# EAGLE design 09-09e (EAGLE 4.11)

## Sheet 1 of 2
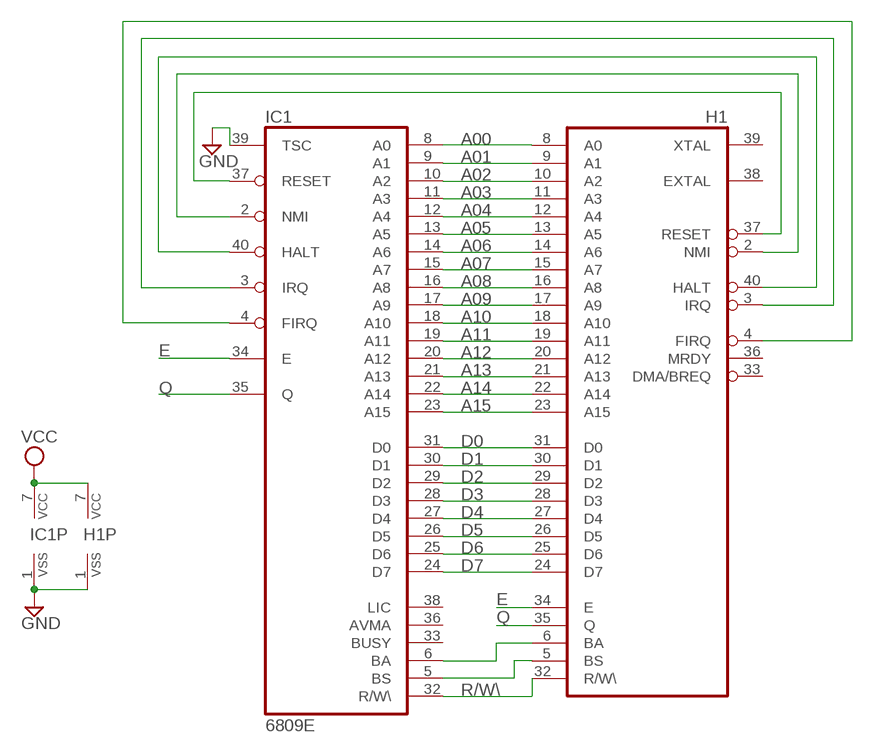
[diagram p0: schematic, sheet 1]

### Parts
H1  6809  [DIL40]
IC1  6809E  [DIL40]

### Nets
A00: H1.8(A0) IC1.8(A0)
A01: H1.9(A1) IC1.9(A1)
A02: H1.10(A2) IC1.10(A2)
A03: H1.11(A3) IC1.11(A3)
A04: H1.12(A4) IC1.12(A4)
A05: H1.13(A5) IC1.13(A5)
A06: H1.14(A6) IC1.14(A6)
A07: H1.15(A7) IC1.15(A7)
A08: H1.16(A8) IC1.16(A8)
A09: H1.17(A9) IC1.17(A9)
A10: H1.18(A10) IC1.18(A10)
A11: H1.19(A11) IC1.19(A11)
A12: H1.20(A12) IC1.20(A12)
A13: H1.21(A13) IC1.21(A13)
A14: H1.22(A14) IC1.22(A14)
A15: H1.23(A15) IC1.23(A15)
D0: H1.31(D0) IC1.31(D0)
D1: H1.30(D1) IC1.30(D1)
D2: H1.29(D2) IC1.29(D2)
D3: H1.28(D3) IC1.28(D3)
D4: H1.27(D4) IC1.27(D4)
D5: H1.26(D5) IC1.26(D5)
D6: H1.25(D6) IC1.25(D6)
D7: H1.24(D7) IC1.24(D7)
E: H1.34(E) IC1.34(E) ; also sheet 2
GND [Power]: H1.1(VSS) IC1.1(VSS) IC1.39(TSC) ; also sheet 2
N$1: H1.5(BS) IC1.5(BS)
N$4: H1.6(BA) IC1.6(BA)
N$5: H1.37(RESET) IC1.37(RESET)
N$6: H1.2(NMI) IC1.2(NMI)
N$8: H1.40(HALT) IC1.40(HALT)
N$9: H1.3(IRQ) IC1.3(IRQ)
N$10: H1.4(FIRQ) IC1.4(FIRQ)
Q: H1.35(Q) IC1.35(Q) ; also sheet 2
R/W\: H1.32(R/W\) IC1.32(R/W\)
VCC [Power]: H1.7(VCC) IC1.7(VCC) ; also sheet 2
Unconnected: H1.33(DMA/BREQ) H1.36(MRDY) H1.38(EXTAL) H1.39(XTAL) IC1.33(BUSY) IC1.36(AVMA) IC1.38(LIC)

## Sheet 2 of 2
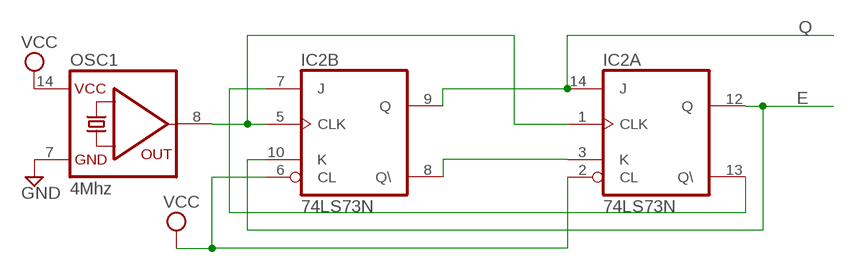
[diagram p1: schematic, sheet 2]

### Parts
IC2  74LS73N  [DIL14]
OSC1  4Mhz  QG5860  [DIL14S]

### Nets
E: IC2.10(B:K) IC2.12(A:Q) ; also sheet 1
GND [Power]: OSC1.7(GND) ; also sheet 1
N$2: IC2.1(A:CLK) IC2.5(B:CLK) OSC1.8(OUT)
N$3: IC2.3(A:K) IC2.8(B:Q\)
N$7: IC2.7(B:J) IC2.13(A:Q\)
Q: IC2.9(B:Q) IC2.14(A:J) ; also sheet 1
VCC [Power]: IC2.2(A:CL) IC2.6(B:CL) OSC1.14(VCC) ; also sheet 1

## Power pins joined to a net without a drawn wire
GND: IC2.11(P:GND)
VCC: IC2.4(P:VCC)

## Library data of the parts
H1 = micro-motorola:6809: MICROCONTROLLER/MEMORY DEVICE
IC1 = micro-motorola:6809E: MICROCONTROLLER/MEMORY DEVICE
IC2 = 74xx-us:74*73: Dual J-K FLIP FLOP, clear
OSC1 = crystal:QG5860: CRYSTAL RESONATOR

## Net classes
1 Power: width 0.508 mm, drill 0.254 mm, clearance 0.254 mm

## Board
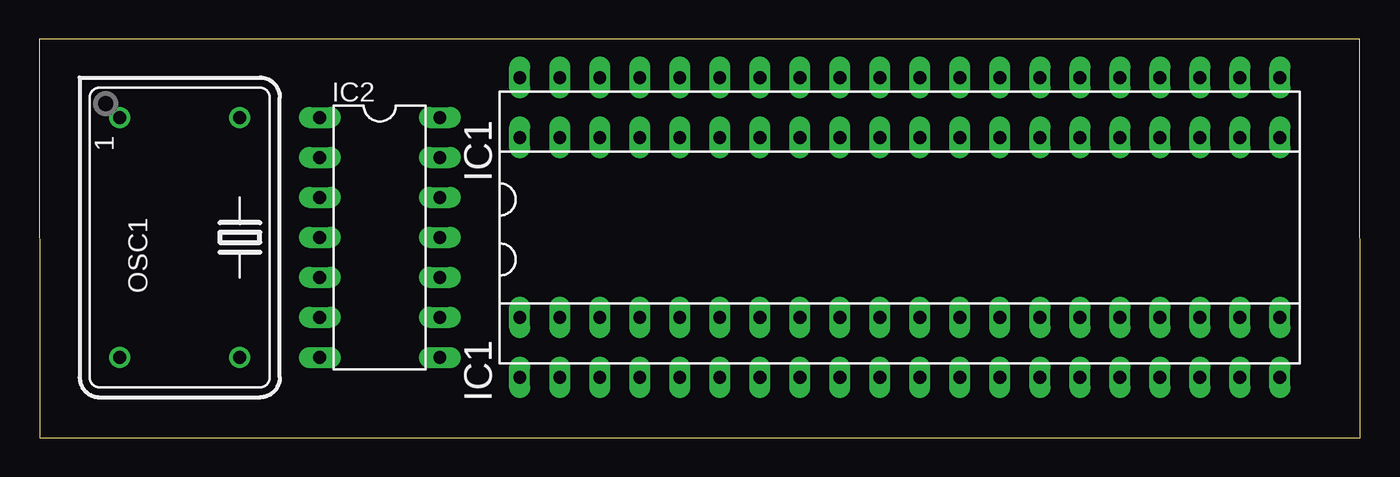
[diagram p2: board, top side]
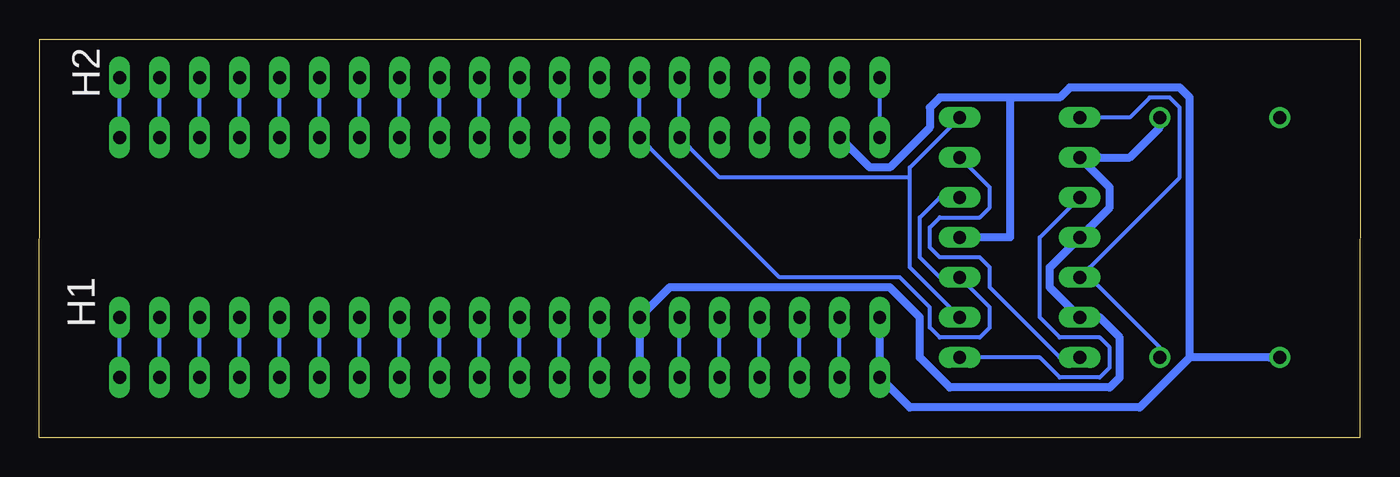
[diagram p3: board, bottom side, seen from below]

Size 83.85 x 25.3 mm. Coordinates in mm from the lower left corner, seen from the top.
Outline: 0.03,0 83.85,0 83.83,25.3 0,25.3 0.03,0
Copper layers (1*16): Top 0.035mm / dielectric 1.5mm / Bottom 0.035mm
Design rules "olimex10mil": minimum track width 10mil, minimum drill 24mil, track to track 10mil, track to pad 10mil, pad to pad 10mil, via to via 10mil, smd to smd 10mil, copper to edge 40mil, drill to drill 10mil, minimum pad ring 10mil, minimum via ring 8mil, stop-mask expansion 0mil, vias tented up to drill 0mil, thermal gap 10mil

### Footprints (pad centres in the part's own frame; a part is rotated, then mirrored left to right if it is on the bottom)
DIL40 = drill 0.813 long: 1 -24.13,-7.62; 2 -21.59,-7.62; 3 -19.05,-7.62; 4 -16.51,-7.62; 5 -13.97,-7.62; 6 -11.43,-7.62; 7 -8.89,-7.62; 8 -6.35,-7.62; 9 -3.81,-7.62; 10 -1.27,-7.62; 11 1.27,-7.62; 12 3.81,-7.62; 13 6.35,-7.62; 14 8.89,-7.62; 15 11.43,-7.62; 16 13.97,-7.62; 17 16.51,-7.62; 18 19.05,-7.62; 19 21.59,-7.62; 20 24.13,-7.62; 21 24.13,7.62; 22 21.59,7.62; 23 19.05,7.62; 24 16.51,7.62; 25 13.97,7.62; 26 11.43,7.62; 27 8.89,7.62; 28 6.35,7.62; 29 3.81,7.62; 30 1.27,7.62; 31 -1.27,7.62; 32 -3.81,7.62; 33 -6.35,7.62; 34 -8.89,7.62; 35 -11.43,7.62; 36 -13.97,7.62; 37 -16.51,7.62; 38 -19.05,7.62; 39 -21.59,7.62; 40 -24.13,7.62
DIL14 = drill 0.813 long: 1 -7.62,-3.81; 2 -5.08,-3.81; 3 -2.54,-3.81; 4 0,-3.81; 5 2.54,-3.81; 6 5.08,-3.81; 7 7.62,-3.81; 8 7.62,3.81; 9 5.08,3.81; 10 2.54,3.81; 11 0,3.81; 12 -2.54,3.81; 13 -5.08,3.81; 14 -7.62,3.81
DIL14S = drill 0.813 round: 1 -7.62,-3.81; 7 7.62,-3.81; 8 7.62,3.81; 14 -7.62,3.81

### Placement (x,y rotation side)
H1  54.63,15.25 0 top
IC1  54.63,11.44 0 top
IC2  21.61,12.71 270 top
OSC1  8.91,12.71 270 top

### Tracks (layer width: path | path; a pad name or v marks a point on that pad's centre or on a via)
A00
  Bottom 0.254: IC1.8 48.28,5.09 48.28,6.36 H1.8
A01
  Bottom 0.254: IC1.9 50.82,5.09 50.82,6.36 H1.9
A02
  Bottom 0.254: IC1.10 53.36,5.09 53.36,6.36 H1.10
A03
  Bottom 0.254: IC1.11 55.9,5.09 55.9,6.36 H1.11
A04
  Bottom 0.254: IC1.12 58.44,5.09 58.44,6.36 H1.12
A05
  Bottom 0.254: IC1.13 60.98,5.09 60.98,6.36 H1.13
A06
  Bottom 0.254: IC1.14 63.52,5.09 63.52,6.36 H1.14
A07
  Bottom 0.254: IC1.15 66.06,5.09 66.06,6.36 H1.15
A08
  Bottom 0.254: IC1.16 68.6,5.09 68.6,6.36 H1.16
A09
  Bottom 0.254: IC1.17 71.14,5.09 71.14,6.36 H1.17
A10
  Bottom 0.254: IC1.18 73.68,5.09 73.68,6.36 H1.18
A11
  Bottom 0.254: IC1.19 76.22,5.09 76.22,6.36 H1.19
A12
  Bottom 0.254: IC1.20 78.76,5.09 78.76,6.36 H1.20
A13
  Bottom 0.254: IC1.21 78.76,20.33 78.76,21.6 H1.21
A14
  Bottom 0.254: IC1.22 76.22,20.33 76.22,21.6 H1.22
A15
  Bottom 0.254: IC1.23 73.68,20.33 73.68,21.6 H1.23
D0
  Bottom 0.254: IC1.31 53.36,20.33 53.36,21.6 H1.31
D1
  Bottom 0.254: IC1.30 55.9,20.33 55.9,21.6 H1.30
D2
  Bottom 0.254: IC1.29 58.44,20.33 58.44,21.6 H1.29
D3
  Bottom 0.254: IC1.28 60.98,20.33 60.98,21.6 H1.28
D4
  Bottom 0.254: IC1.27 63.52,20.33 63.52,21.6 H1.27
D5
  Bottom 0.254: IC1.26 66.06,20.33 66.06,21.6 H1.26
D6
  Bottom 0.254: IC1.25 68.6,20.33 68.6,21.6 H1.25
D7
  Bottom 0.254: IC1.24 71.14,20.33 71.14,21.6 H1.24
E
  Bottom 0.254: H1.34 45.74,21.6 45.74,20.33 IC1.34 45.11,18.43 36.85,10.17 29.23,10.17 27.33,8.27 27.33,7 26.69,6.36 24.15,6.36 23.52,7 23.52,8.27 24.79,9.54 IC2.10 | IC2.10 26.69,10.17 | 26.69,10.17 27.96,11.44 27.96,13.98 26.69,15.25 IC2.12 | IC2.10 26.69,10.17
GND
  Bottom 0.508: 10.82,5.09 5.74,5.09 OSC1.7 | 10.82,5.09 13.99,1.92 28.6,1.92 29.87,3.19 IC1.1 30.5,5.09 30.5,6.36 H1.1 | 10.82,5.09 10.82,21.6 11.45,22.24 18.44,22.24 19.07,21.6 22.25,21.6 | 22.25,21.6 26.69,21.6 27.33,20.97 27.33,19.7 29.87,17.16 31.14,17.16 32.41,18.43 IC1.39 | 22.25,21.6 22.22,12.71 24.35,12.71 IC2.11
N$1
  Bottom 0.254: IC1.5 40.66,5.09 40.66,6.36 H1.5
N$2
  Bottom 0.254: OSC1.8 12.72,5.73 17.17,10.17 IC2.5 17.17,10.81 11.45,16.52 11.45,20.97 12.09,21.6 13.36,21.6 14.63,20.33 16.53,20.33 IC2.1
N$3
  Bottom 0.254: IC2.8 24.15,5.09 20.34,5.09 19.07,3.82 16.53,3.82 15.9,4.46 15.9,5.73 16.53,6.36 19.07,6.36 20.34,7.63 20.34,12.71 18.44,14.62 IC2.3
N$4
  Bottom 0.254: IC1.6 43.2,5.09 43.2,6.36 H1.6
N$5
  Bottom 0.254: IC1.37 38.12,20.33 38.12,21.6 H1.37
N$6
  Bottom 0.254: IC1.2 33.04,5.09 33.04,6.36 H1.2
N$7
  Bottom 0.254: IC2.7 19.07,5.09 23.52,9.54 23.52,10.81 24.15,11.44 26.69,11.44 27.33,12.08 27.33,13.35 26.69,13.98 24.15,13.98 23.52,14.62 23.52,15.89 24.79,17.16 IC2.13
N$8
  Bottom 0.254: IC1.40 30.5,20.33 30.5,21.6 H1.40
N$9
  Bottom 0.254: IC1.3 35.58,5.09 35.58,6.36 H1.3
N$10
  Bottom 0.254: IC1.4 38.12,5.09 38.12,6.36 H1.4
Q
  Bottom 0.254: H1.35 43.2,21.6 43.2,20.33 IC1.35 42.57,18.43 40.66,16.52 28.6,16.52 | 28.6,16.52 28.6,17.16 26.06,19.7 IC2.14 | 28.6,16.52 28.6,10.81 26.06,8.27 IC2.9
R/W\
  Bottom 0.254: IC1.32 50.82,20.33 50.82,21.6 H1.32
VCC
  Bottom 0.508: OSC1.14 12.72,19.7 14.63,17.79 16.53,17.79 IC2.2 17.17,17.16 15.9,15.89 15.9,14.62 17.17,13.35 IC2.4 18.44,12.08 19.71,10.81 19.71,9.54 18.44,8.27 IC2.6 16.53,7.63 15.26,6.36 15.26,3.82 15.9,3.19 26.06,3.19 27.96,5.09 27.96,7.63 29.87,9.54 43.84,9.54 45.11,8.27 H1.7 45.74,6.36 45.74,5.09 IC1.7

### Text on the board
bPlace: H2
